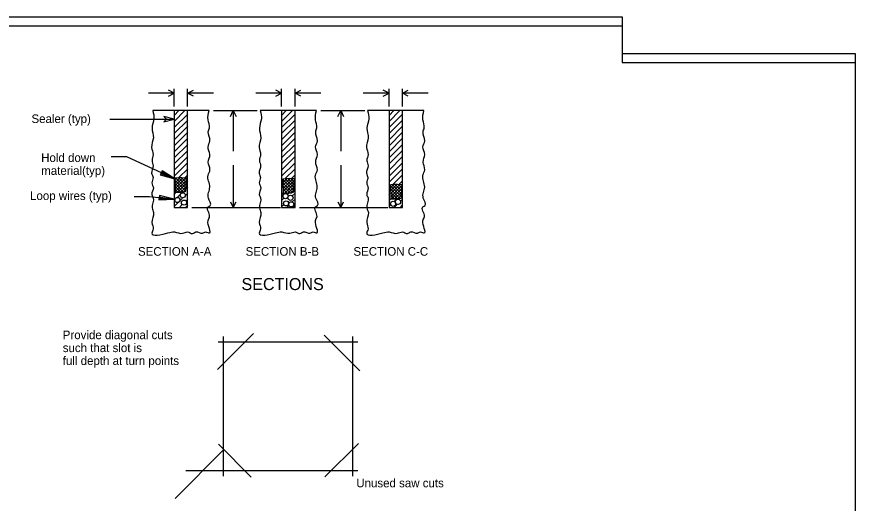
# Model space of a CAD drawing. Extents: x 0 to 390, y 0 to 265.
# Drawn here: x 160.8 to 390, y 132.1 to 265 of the extents above; entities that cross this region are included whole.
import ezdxf

# ---------------------------------------------------------------- set-up
doc = ezdxf.new("R2010")
doc.units = 0
doc.layers.add('D_Details', color=7, linetype='Continuous')
doc.layers.add('Default', color=7, linetype='Continuous')

msp = doc.modelspace()

# ---------------------------------------------------------------- linework, layer by layer
at = {"layer": 'D_Details'}
for p, q in [((203.83, 240.52), (203.83, 245.3)), ((207.5, 240.52), (207.5, 245.3)), ((233.19, 240.52), (233.19, 245.3)), ((236.87, 240.52), (236.87, 245.3)), ((262.56, 240.52), (262.56, 245.3)), ((266.23, 240.52), (266.23, 245.3)), ((203.83, 244.13), (196.78, 244.13)), ((214.55, 244.13), (207.5, 244.13)), ((233.19, 244.13), (226.14, 244.13)), ((243.92, 244.13), (236.87, 244.13)), ((262.56, 244.13), (255.51, 244.13)), ((273.28, 244.13), (266.23, 244.13)), ((203.83, 239.35), (197.95, 239.35)), ((213.38, 239.35), (207.5, 239.35)), ((214.55, 239.35), (226.53, 239.35)), ((219.98, 239.35), (219.98, 228.29)), ((233.19, 239.35), (227.32, 239.35)), ((242.74, 239.35), (236.87, 239.35)), ((243.92, 239.35), (255.9, 239.35)), ((249.34, 239.35), (249.34, 228.29)), ((262.56, 239.35), (256.68, 239.35)), ((272.11, 239.35), (266.23, 239.35)), ((186.23, 237.04), (203.83, 237.04)), ((203.83, 237.04), (201.01, 237.74)), ((201.01, 237.74), (201.71, 237.04)), ((201.71, 237.04), (201.01, 236.31)), ((201.01, 236.31), (203.83, 237.04)), ((186.64, 226.83), (190.75, 226.83)), ((190.75, 226.83), (204.03, 220.69)), ((200.52, 222.89), (200.03, 221.83)), ((200.52, 222.89), (200.03, 221.83)), ((200.52, 222.89), (200.03, 221.83)), ((200.34, 222.5), (201.62, 221.77)), ((200.34, 222.5), (201.62, 221.77)), ((200.34, 222.5), (201.62, 221.77)), ((200.4, 222.62), (203.1, 221.12)), ((200.4, 222.62), (203.1, 221.12)), ((200.4, 222.62), (203.1, 221.12)), ((204.03, 220.69), (200.52, 222.89)), ((204.03, 220.69), (200.52, 222.89)), ((204.03, 220.69), (200.52, 222.89)), ((219.98, 224.43), (219.98, 212.92)), ((249.34, 224.43), (249.34, 212.92)), ((200.03, 221.83), (204.03, 220.69)), ((200.03, 221.83), (204.03, 220.69)), ((200.03, 221.83), (204.03, 220.69)), ((203.1, 221.12), (200.15, 222.09)), ((203.1, 221.12), (200.15, 222.09)), ((203.1, 221.12), (200.15, 222.09)), ((201.62, 221.77), (200.21, 222.23)), ((201.62, 221.77), (200.21, 222.23)), ((201.62, 221.77), (200.21, 222.23)), ((192.89, 215.89), (197, 215.89)), ((197, 215.89), (203.82, 215.17)), ((199.79, 216.13), (199.66, 214.96)), ((199.75, 215.69), (201.19, 215.42)), ((199.76, 215.84), (202.8, 215.28)), ((203.82, 215.17), (199.79, 216.13)), ((199.66, 214.96), (203.82, 215.17)), ((202.8, 215.28), (199.7, 215.25)), ((201.19, 215.42), (199.71, 215.39)), ((208.68, 212.92), (232.89, 212.92)), ((238.04, 212.92), (262.26, 212.92)), ((225.53, 178.48), (215.64, 168.59)), ((217.34, 139.46), (217.34, 177.64)), ((254.59, 168.28), (244.84, 178.04)), ((252.58, 177.64), (252.58, 139.46)), ((215.87, 176.17), (254.05, 176.17)), ((224.9, 139.24), (215.94, 148.2)), ((254.19, 148.42), (245.05, 139.27)), ((204.11, 133.41), (217.34, 146.64)), ((254.05, 140.93), (207.04, 140.93))]:
    msp.add_line(p, q, dxfattribs=at)
for points in [[(202.26, 243.35), (203.83, 244.13), (202.26, 244.91)], [(209.07, 243.35), (207.5, 244.13), (209.07, 244.91)], [(231.62, 243.35), (233.19, 244.13), (231.62, 244.91)], [(238.44, 243.35), (236.87, 244.13), (238.44, 244.91)], [(260.99, 243.35), (262.56, 244.13), (260.99, 244.91)], [(267.8, 243.35), (266.23, 244.13), (267.8, 244.91)], [(203.83, 236.41), (206.76, 239.35)], [(203.83, 238.07), (205.11, 239.35)], [(203.83, 234.74), (207.52, 238.43)], [(219.2, 237.78), (219.98, 239.35), (220.76, 237.78)], [(233.19, 236.41), (236.13, 239.35)], [(233.19, 238.07), (234.47, 239.35)], [(233.19, 234.74), (236.88, 238.43)], [(248.56, 237.78), (249.34, 239.35), (250.12, 237.78)], [(262.56, 236.41), (265.49, 239.35)], [(262.56, 238.07), (263.84, 239.35)], [(262.56, 234.74), (266.25, 238.43)], [(203.83, 233.08), (207.52, 236.77)], [(233.19, 233.08), (236.88, 236.77)], [(262.56, 233.08), (266.25, 236.77)], [(203.83, 231.42), (207.52, 235.11)], [(233.19, 231.42), (236.88, 235.11)], [(262.56, 231.42), (266.25, 235.11)], [(203.82, 228.09), (207.52, 231.79)], [(203.83, 229.76), (207.52, 233.45)], [(233.18, 228.09), (236.88, 231.79)], [(233.19, 229.76), (236.88, 233.45)], [(262.55, 228.09), (266.25, 231.79)], [(262.56, 229.76), (266.25, 233.45)], [(203.83, 226.44), (207.52, 230.12)], [(233.19, 226.44), (236.88, 230.12)], [(262.56, 226.44), (266.25, 230.12)], [(203.83, 224.78), (207.52, 228.47)], [(233.19, 224.78), (236.88, 228.47)], [(262.56, 224.78), (266.25, 228.47)], [(203.83, 223.11), (207.52, 226.8)], [(203.83, 221.46), (207.5, 225.13)], [(233.19, 223.11), (236.88, 226.8)], [(233.19, 221.46), (236.87, 225.13)], [(262.56, 223.11), (266.25, 226.8)], [(262.56, 221.46), (266.23, 225.13)], [(205.11, 221.07), (207.52, 223.48)], [(234.11, 220.7), (236.88, 223.48)], [(262.56, 219.79), (266.25, 223.48)], [(204.04, 220.48), (204.46, 220.92)], [(204.04, 220.32), (207.01, 217.34), (207.02, 217.33)], [(204.05, 219.67), (205.35, 220.97)], [(204.06, 218.86), (206.18, 220.96)], [(204.09, 218.05), (206.96, 220.92)], [(204.1, 217.23), (207.17, 220.3)], [(204.3, 220.89), (207.07, 218.12)], [(205.05, 220.96), (207.1, 218.92)], [(205.86, 220.99), (207.14, 219.71)], [(206.72, 221.02), (207.52, 221.82)], [(206.75, 220.93), (207.19, 220.49)], [(207.17, 219.82), (207.52, 220.16)], [(233.19, 219.79), (233.56, 220.15)], [(233.52, 220.48), (233.71, 220.66)], [(233.53, 220.5), (236.55, 217.49)], [(233.54, 219.67), (234.63, 220.74)], [(233.57, 218.86), (235.47, 220.76)], [(233.58, 218.05), (236.23, 220.7)], [(233.6, 217.23), (236.69, 220.32)], [(234.16, 220.72), (236.59, 218.27)], [(234.94, 220.75), (236.63, 219.07)], [(235.73, 220.67), (236.88, 221.82)], [(235.79, 220.74), (236.67, 219.87)], [(236.65, 219.93), (236.88, 220.16)], [(236.68, 220.68), (236.72, 220.65)], [(263.71, 219.28), (266.25, 221.82)], [(265.25, 219.17), (266.25, 220.16)], [(203.83, 219.79), (204.05, 220.01)], [(203.83, 218.13), (204.12, 218.43)], [(204.05, 219.47), (206.41, 217.11)], [(204.06, 218.63), (205.62, 217.06)], [(204.1, 217.77), (204.81, 217.05)], [(204.74, 217.05), (207.13, 219.42)], [(205.6, 217.06), (207.08, 218.55)], [(207.13, 218.11), (207.52, 218.5)], [(233.19, 218.13), (233.65, 218.59)], [(233.54, 219.66), (236.21, 217)], [(233.57, 218.81), (235.52, 216.86)], [(233.59, 217.96), (234.72, 216.83)], [(234.03, 216.83), (236.65, 219.45)], [(234.86, 216.83), (236.61, 218.58)], [(236.53, 218.14), (236.88, 218.5)], [(262.56, 218.13), (262.86, 218.44)], [(262.96, 218.81), (265.98, 215.81)], [(262.97, 218.28), (263.84, 219.15)], [(262.97, 217.97), (265.55, 215.38)], [(262.99, 217.47), (264.7, 219.18)], [(263, 216.66), (265.48, 219.13)], [(263.03, 215.84), (266.13, 218.95)], [(263.25, 215.24), (266.08, 218.07)], [(263.5, 219.11), (266.01, 216.59)], [(264.27, 219.17), (266.05, 217.39)], [(265.11, 219.15), (266.09, 218.18)], [(266, 219.11), (266.14, 218.95)], [(266.03, 218.28), (266.25, 218.5)], [(203.83, 216.48), (204.4, 217.05)], [(203.83, 213.15), (206.14, 215.47)], [(204.67, 215.65), (206.08, 217.06)], [(206.51, 217.15), (207.05, 217.67)], [(206.92, 216.24), (207.52, 216.84)], [(233.19, 216.48), (233.65, 216.93)], [(233.19, 214.81), (233.84, 215.46)], [(233.6, 217.11), (233.89, 216.83)], [(234.83, 216.45), (235.18, 216.79)], [(235.73, 216.87), (236.56, 217.71)], [(236.1, 216.06), (236.88, 216.84)], [(262.56, 216.48), (262.88, 216.79)], [(262.99, 217.12), (264.84, 215.28)], [(263.02, 216.26), (264.05, 215.24)], [(264.07, 215.24), (266.03, 217.2)], [(264.94, 215.28), (266, 216.32)], [(265.62, 216.21), (266.23, 216.83)], [(203.83, 214.81), (203.96, 214.94)], [(205.25, 212.92), (206, 213.67)], [(206.92, 212.92), (207.52, 213.52)], [(207.09, 214.75), (207.52, 215.17)], [(219.2, 214.48), (219.98, 212.92), (220.76, 214.48)], [(233.19, 213.15), (233.76, 213.72)], [(234.61, 212.92), (235.16, 213.45)], [(236.11, 214.4), (236.88, 215.17)], [(236.28, 212.92), (236.88, 213.52)], [(248.56, 214.48), (249.34, 212.92), (250.12, 214.48)], [(262.56, 214.81), (263.1, 215.35)], [(262.56, 213.15), (263.03, 213.63)], [(263.03, 215.43), (263.22, 215.24)], [(263.96, 214.56), (264.65, 215.24)], [(263.98, 212.92), (264.82, 213.74)], [(265.65, 212.92), (266.25, 213.52)], [(265.69, 214.63), (266.25, 215.17)]]:
    msp.add_lwpolyline(points, dxfattribs=at)
for points in [[(203.83, 239.35), (203.83, 212.92), (207.5, 212.92), (207.5, 239.35)], [(233.19, 239.35), (233.19, 212.92), (236.87, 212.92), (236.87, 239.35)], [(262.56, 239.35), (262.56, 212.92), (266.23, 212.92), (266.23, 239.35)], [(204.1, 217.05), (205.3, 217.05), (206.4, 217.1), (207.03, 217.36), (207.13, 219.45), (207.21, 220.9), (205.91, 221), (204.97, 220.96), (204.01, 220.87)], [(233.6, 216.83), (234.8, 216.83), (235.91, 216.87), (236.54, 217.13), (236.63, 219.22), (236.72, 220.68), (235.41, 220.77), (234.47, 220.74), (233.52, 220.65)], [(263.03, 215.24), (264.23, 215.24), (265.33, 215.29), (265.96, 215.55), (266.06, 217.64), (266.14, 219.09), (264.84, 219.19), (263.9, 219.15), (262.95, 219.06)]]:
    msp.add_lwpolyline(points, close=True, dxfattribs=at)
for centre in [(204.71, 214.93), (206.16, 216.23), (234.29, 216), (235.61, 215.54), (206.52, 214.23), (234.43, 214.01), (235.82, 213.76), (263.7, 213.91), (265.01, 214.43)]:
    msp.add_circle(centre, 0.705, dxfattribs=at)
for points in [[(197.95, 239.35), (198.29, 237.11), (197.77, 234.58), (198.13, 231.93), (197.66, 229.29), (198.08, 227.38), (197.77, 225.67), (198.08, 224.28), (197.66, 222.27), (198.04, 221.07), (197.72, 219.62), (198.13, 218.23), (197.72, 216.41), (198.08, 215.54), (197.77, 212.79), (198.19, 211.5), (197.72, 208.75), (198.08, 207.04), (197.72, 205.9), (202.11, 205.95), (203.87, 206.21), (206.11, 205.85), (207.49, 206.21), (208.84, 205.8), (209.77, 206.21), (211.58, 205.9), (212.41, 206.21), (213.46, 205.95), (213.09, 209.32), (213.51, 210.45), (213.09, 213.1), (213.67, 213.47), (213.2, 215.43), (213.56, 218.47), (213.09, 221.69), (213.61, 223.18), (213.14, 225.31), (213.61, 227.38), (213.09, 229.44), (213.61, 231.11), (213.14, 233.55), (213.46, 234.68), (213.09, 236.8), (213.38, 239.35)], [(227.32, 239.35), (227.66, 237.11), (227.13, 234.58), (227.5, 231.93), (227.03, 229.29), (227.45, 227.38), (227.13, 225.67), (227.45, 224.28), (227.03, 222.27), (227.4, 221.07), (227.08, 219.62), (227.5, 218.23), (227.08, 216.41), (227.45, 215.54), (227.13, 212.79), (227.55, 211.5), (227.08, 208.75), (227.45, 207.04), (227.08, 205.9), (231.48, 205.95), (233.24, 206.21), (235.47, 205.85), (236.86, 206.21), (238.21, 205.8), (239.14, 206.21), (240.94, 205.9), (241.78, 206.21), (242.82, 205.95), (242.46, 209.32), (242.87, 210.45), (242.46, 213.1), (243.04, 213.47), (242.57, 215.43), (242.93, 218.47), (242.46, 221.69), (242.98, 223.18), (242.51, 225.31), (242.98, 227.38), (242.46, 229.44), (242.98, 231.11), (242.51, 233.55), (242.82, 234.68), (242.46, 236.8), (242.74, 239.35)], [(256.68, 239.35), (257.03, 237.11), (256.5, 234.58), (256.86, 231.93), (256.39, 229.29), (256.81, 227.38), (256.5, 225.67), (256.81, 224.28), (256.39, 222.27), (256.77, 221.07), (256.45, 219.62), (256.86, 218.23), (256.45, 216.41), (256.81, 215.54), (256.5, 212.79), (256.92, 211.5), (256.45, 208.75), (256.81, 207.04), (256.45, 205.9), (260.84, 205.95), (262.6, 206.21), (264.84, 205.85), (266.22, 206.21), (267.57, 205.8), (268.5, 206.21), (270.31, 205.9), (271.14, 206.21), (272.19, 205.95), (271.83, 209.32), (272.24, 210.45), (271.83, 213.1), (272.4, 213.47), (271.93, 215.43), (272.3, 218.47), (271.83, 221.69), (272.34, 223.18), (271.87, 225.31), (272.34, 227.38), (271.83, 229.44), (272.34, 231.11), (271.87, 233.55), (272.19, 234.68), (271.83, 236.8), (272.11, 239.35)]]:
    msp.add_spline(points, degree=3, dxfattribs=at)
at = {"layer": 'Default'}
for points in [[(0, 265), (326.25, 265), (326.25, 255), (390, 255), (390, 37.5), (315, 37.5), (315, 0), (0, 0)], [(0, 262.5), (326.25, 262.5), (326.25, 252.5), (390, 252.5), (390, 40), (315, 40), (315, 2.5), (0, 2.5)]]:
    msp.add_lwpolyline(points, close=True, dxfattribs=at)

# ---------------------------------------------------------------- texts
at = {"layer": 'D_Details'}
for s, height, p in [('Sealer (typ)', 2.3493, (164.82, 235.97)), ('Hold down', 2.349, (167.47, 225.33)), ('material(typ)', 2.3493, (167.47, 221.8)), ('Loop wires (typ)', 2.3493, (164.44, 214.93)), ('SECTION A-A', 2.3493, (193.93, 199.71)), ('SECTION B-B', 2.3493, (223.35, 199.71)), ('SECTION C-C', 2.3493, (252.83, 199.71)), ('SECTIONS', 3.289, (222.23, 190.32)), ('Provide diagonal cuts', 2.3493, (173.37, 176.91)), ('such that slot is', 2.3493, (173.37, 173.38)), ('full depth at turn points', 2.3493, (173.37, 169.86)), ('Unused saw cuts', 2.3493, (253.61, 136.44))]:
    msp.add_text(s, height=height, dxfattribs=at).set_placement(p)

doc.saveas('drawing.dxf')
